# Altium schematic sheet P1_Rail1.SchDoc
size 368 x 228 mm
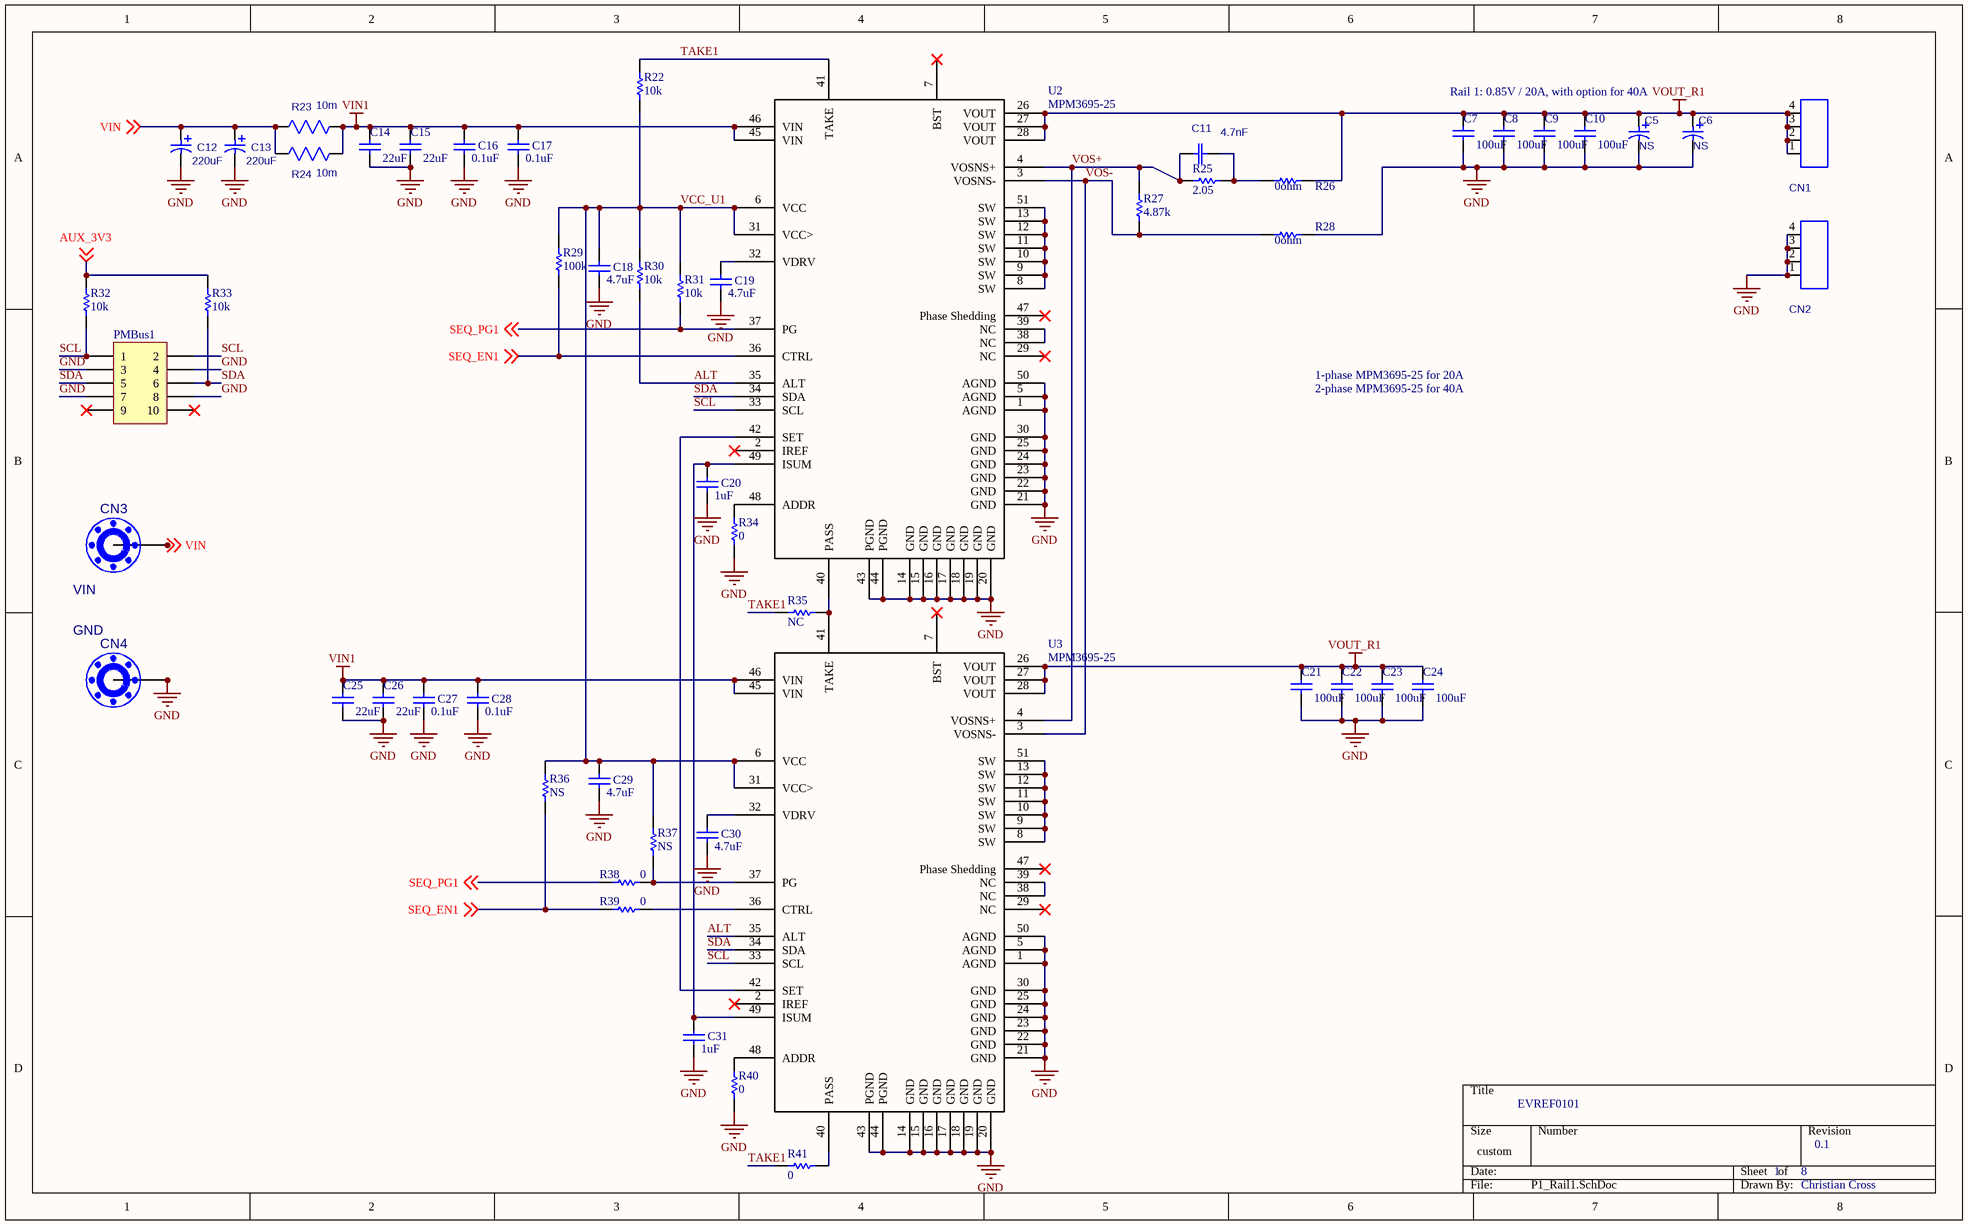
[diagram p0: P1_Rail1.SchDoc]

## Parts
C5  value NS  [POSCAP/D2]  (hidden comment: POSCAP/D2-D4)
C6  value NS  [POSCAP/D2]  (hidden comment: POSCAP/D2-D4)
C7  100uF  [CAP/1210]
C8  100uF  [CAP/1210]
C9  100uF  [CAP/1210]
C10  100uF  [CAP/1210]
C11  4.7nF  [CAP0603]
C12  220uF  [CAP/OD8.0P3.5]
C13  220uF  [CAP/OD8.0P3.5]
C14  22uF  [CAP/1210]
C15  22uF  [CAP/1210]
C16  0.1uF  [CAP0402]
C17  0.1uF  [CAP0402]
C18  4.7uF  [CAP/0603]
C19  4.7uF  [CAP/0603]
C20  1uF  [CAP/0603]
C21  100uF  [CAP/1210]
C22  100uF  [CAP/1210]
C23  100uF  [CAP/1210]
C24  100uF  [CAP/1210]
C25  22uF  [CAP/1210]
C26  22uF  [CAP/1210]
C27  0.1uF  [CAP0402]
C28  0.1uF  [CAP0402]
C29  4.7uF  [CAP/0603]
C30  4.7uF  [CAP/0603]
C31  1uF  [CAP/0603]
CN1  VOUT_R1  [KEYSTONE-7697-75]  (value not drawn)
CN2  GND  [KEYSTONE-7697-75]  (value not drawn)
CN3  VIN  [BANANA-K575]
CN4  GND  [BANANA-K575]
PMBus1  Header 5X2  [HDR2X5]  (value not drawn)
R22  10k  [RES/0603]
R23  10m  [RES2512]
R24  10m  [RES2512]
R25  2.05  [RES/0603]
R26  0ohm  [RES/0603]
R27  4.87k  [RES/0603]
R28  0ohm  [RES/0603]
R29  100k  [RES/0603]
R30  10k  [RES/0603]
R31  10k  [RES/0603]
R32  10k  [RES/0603]
R33  10k  [RES/0603]
R34  0  [RES/0603]
R35  NC  [RES/0603]
R36  NS  [RES/0603]
R37  NS  [RES/0603]
R38  0  [RES/0603]
R39  0  [RES/0603]
R40  0  [RES/0603]
R41  0  [RES/0603]
U2  MPM3695-25  [MPM3695-25 - ROY]
U3  MPM3695-25  [MPM3695-25 - ROY]

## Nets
GND: C5.2 C6.2 C7.1 C8.1 C9.1 C10.1 C12.2 C13.2 C14.1 C15.1 C16.1 C17.1 C18.1 C19.1 C20.1 C21.1 C22.1 C23.1 C24.1 C25.1 C26.1 C27.1 C28.1 C29.1 C30.1 C31.1 CN2.1 CN2.2 CN2.3 CN2.4 CN4.1 CN4.2 CN4.3 CN4.4 CN4.5 CN4.6 CN4.7 CN4.8 CN4.9 PMBus1.3 PMBus1.4 PMBus1.7 PMBus1.8 R28.2 R34.2 R40.1 U2.1(AGND) U2.5(AGND) U2.14(GND) U2.15(GND) U2.16(GND) U2.17(GND) U2.18(GND) U2.19(GND) U2.20(GND) U2.21(GND) U2.22(GND) U2.23(GND) U2.24(GND) U2.25(GND) U2.30(GND) U2.43(PGND) U2.44(PGND) U2.50(AGND) U3.1(AGND) U3.5(AGND) U3.14(GND) U3.15(GND) U3.16(GND) U3.17(GND) U3.18(GND) U3.19(GND) U3.20(GND) U3.21(GND) U3.22(GND) U3.23(GND) U3.24(GND) U3.25(GND) U3.30(GND) U3.43(PGND) U3.44(PGND) U3.50(AGND)
VIN1: C14.2 C15.2 C16.2 C17.2 C25.2 C26.2 C27.2 C28.2 R23.2 R24.2 U2.45(VIN) U2.46(VIN) U3.45(VIN) U3.46(VIN)
VOUT_R1: C5.1 C6.1 C7.2 C8.2 C9.2 C10.2 C21.2 C22.2 C23.2 C24.2 CN1.1 CN1.2 CN1.3 CN1.4 R26.2 U2.26(VOUT) U2.27(VOUT) U2.28(VOUT) U3.26(VOUT) U3.27(VOUT) U3.28(VOUT)
ALT: R30.2 U2.35(ALT) U3.35(ALT)
AUX_3V3: R32.1 R33.2 ; off-sheet AUX_3V3
SCL: PMBus1.1 PMBus1.2 R32.2 U2.33(SCL) U3.33(SCL)
SDA: PMBus1.5 PMBus1.6 R33.1 U2.34(SDA) U3.34(SDA)
SEQ_EN1: R29.2 R36.2 R39.1 U2.36(CTRL) ; off-sheet SEQ_EN1
SEQ_PG1: R31.2 R38.1 U2.37(PG) ; off-sheet SEQ_PG1
TAKE1: R22.1 R35.1 R41.2 U2.41(TAKE)
VCC_U1: C18.2 C29.2 R22.2 R29.1 R30.1 R31.1 R36.1 R37.1 U2.6(VCC) U2.31(VCC>) U3.6(VCC) U3.31(VCC>)
VIN: C12.1 C13.1 CN3.1 CN3.2 CN3.3 CN3.4 CN3.5 CN3.6 CN3.7 CN3.8 CN3.9 R23.1 R24.1 ; off-sheet VIN
VOS+: C11.1 R25.2 R27.2 U2.4(VOSNS+) U3.4(VOSNS+)
VOS-: R27.1 R28.1 U2.3(VOSNS-) U3.3(VOSNS-)
NetC11_2: C11.2 R25.1 R26.1
NetC19_2: C19.2 U2.32(VDRV)
NetC20_2: C20.2 C31.2 U2.49(ISUM) U3.49(ISUM)
NetC30_2: C30.2 U3.32(VDRV)
NetR34_1: R34.1 U2.48(ADDR)
NetR35_2: R35.2 U2.40(PASS) U3.41(TAKE)
NetR37_2: R37.2 R38.2 U3.37(PG)
NetR39_2: R39.2 U3.36(CTRL)
NetR40_2: R40.2 U3.48(ADDR)
NetR41_1: R41.1 U3.40(PASS)
NetU2_8: U2.8(SW) U2.9(SW) U2.10(SW) U2.11(SW) U2.12(SW) U2.13(SW) U2.51(SW)
NetU2_38: U2.38(NC) U2.39(NC)
NetU2_42: U2.42(SET) U3.42(SET)
NetU3_8: U3.8(SW) U3.9(SW) U3.10(SW) U3.11(SW) U3.12(SW) U3.13(SW) U3.51(SW)
NetU3_38: U3.38(NC) U3.39(NC)

Not connected (* = marked no-connect by the designer): PMBus1 9* 10*; U2 2(IREF)* 7(BST)* 29(NC)* 47(Phase_Shedding)*; U3 2(IREF)* 7(BST)* 29(NC)* 47(Phase_Shedding)*

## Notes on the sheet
- Rail 1: 0.85V / 20A, with option for 40A
- 1-phase MPM3695-25 for 20A
- 2-phase MPM3695-25 for 40A
- EVREF0101
- 1
- 8
- 0.1
- Christian Cross

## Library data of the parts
C5 C6 = POSCAP/D2-D4: {Description}; Manufacturer P/N: {Manufacturer P/N}; Manufacturer: {Manufacturer}
C7-C10 C14-C31 = Cap: Capacitor
C11 = CAP0603: {Description}; Manufacturer: {Manufacturer}; Manufacturer P/N: {Manufacturer P/N}
C12 C13 = CAP/OD8.0P3.5: {Description}; Manufacturer P/N: {Manufacturer P/N}; Manufacturer: {Manufacturer}
CN1 CN2 = KEYSTONE7697-75: {Description}; Manufacturer P/N: {Manufacturer P/N}; Manufacturer: {Manufacturer}
CN3 CN4 = BANANA-K575: Connector, RCA Jack, R/A; Manufacturer P/N: RCJ-012; Manufacturer: CUI, Inc.
PMBus1 = Header 5X2: Header, 5-Pin, Dual row
R22 R26-R33 R36 R37 = Res1: Resistor
R23 R24 = RES2512: {Description}; Manufacturer P/N: {Manufacturer P/N}; Manufacturer: {Manufacturer}
R25 = Res1: Resistor; Value: 2.05k
R34 R38-R41 = Res1: Resistor; Value: 0ohm
R35 = Res1: Resistor; Value: NS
